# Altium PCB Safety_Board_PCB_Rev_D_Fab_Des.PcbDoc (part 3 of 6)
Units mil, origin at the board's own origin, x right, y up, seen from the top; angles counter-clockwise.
Board outline 11000 x 4400 mil, 6 copper layers (L1-TOP, L2-Plane, L3-Signal, L4-Signal, L5-Plane, L6-BOT); 712 components, 540 nets, 2214 pads, 875 vias.
Unrouted connection lines stored in the file: 3.
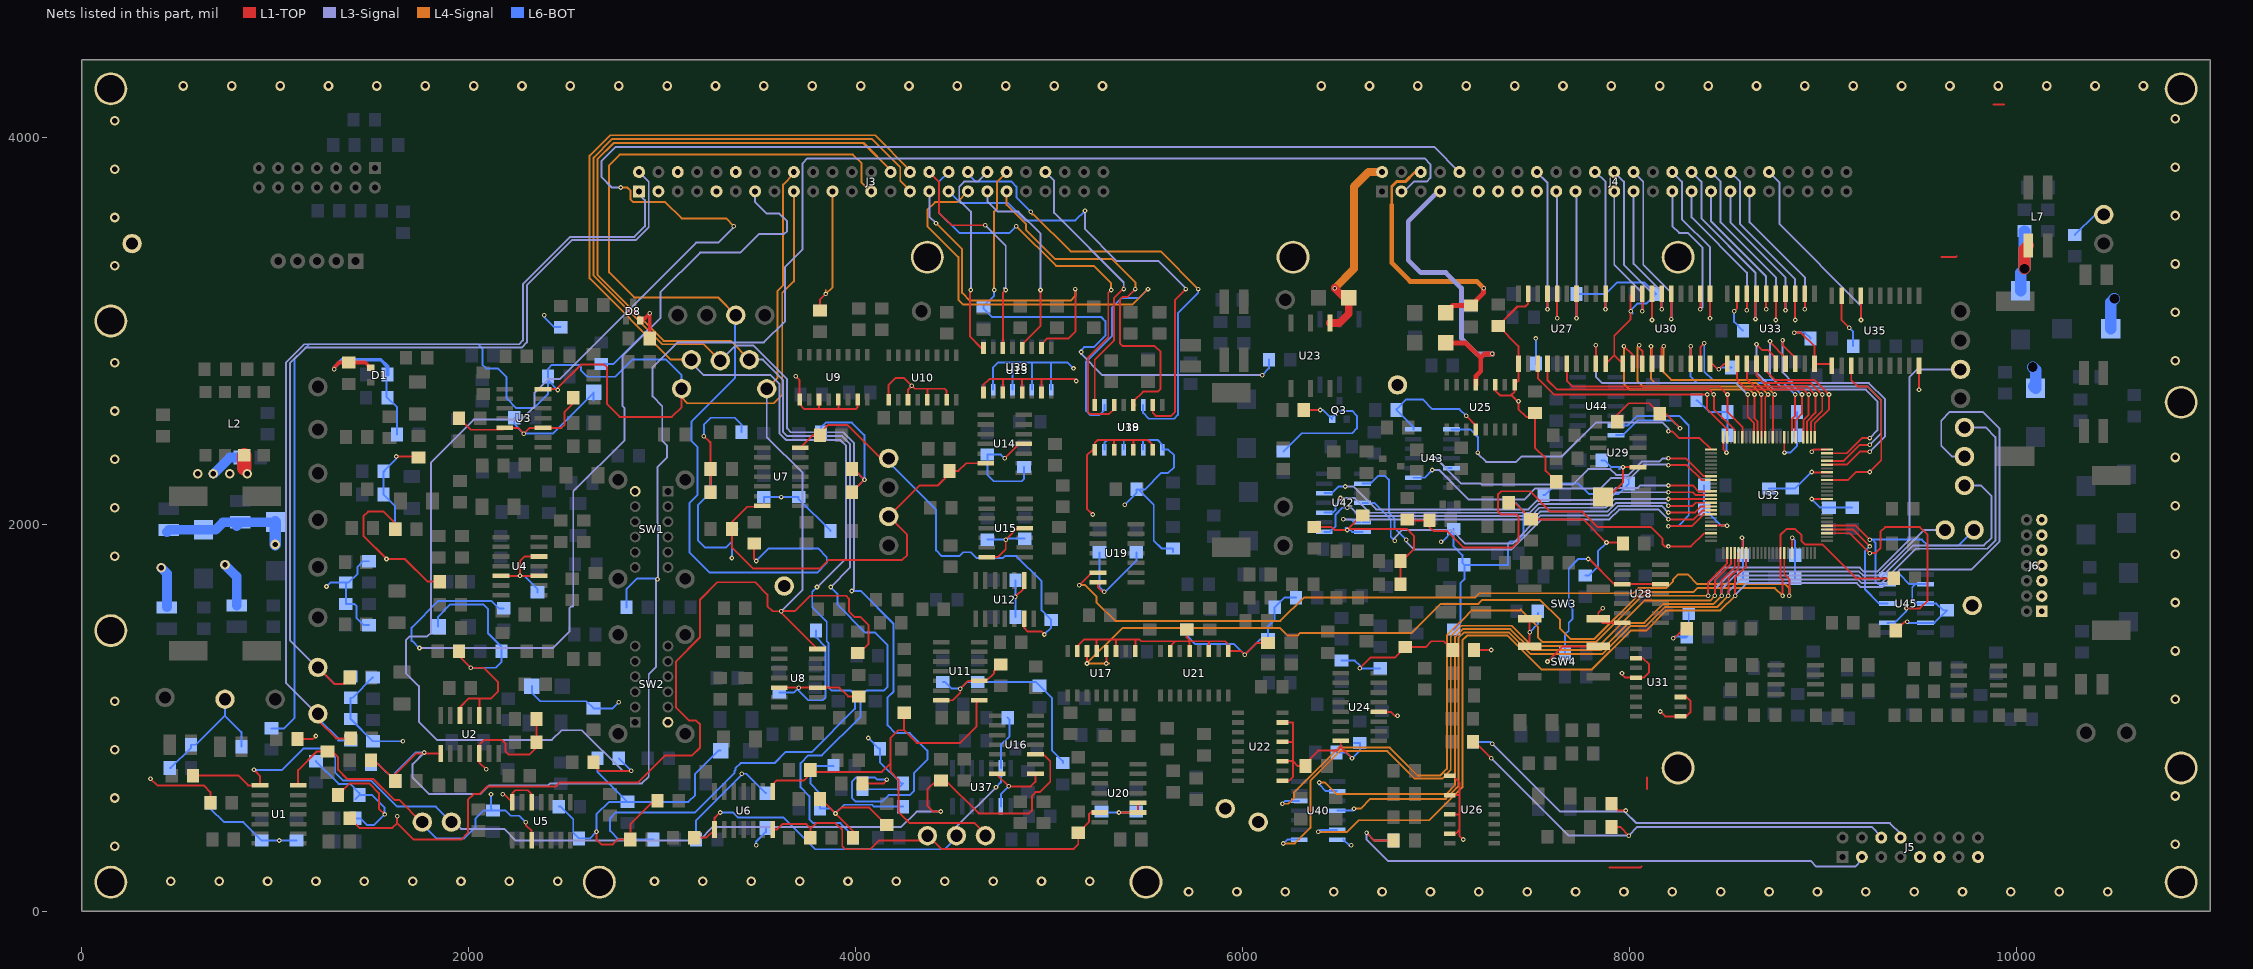
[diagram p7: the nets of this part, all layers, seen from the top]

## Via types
v1: diameter 24, hole 12, L1-TOP to L6-BOT, 720 vias
v2: diameter 50, hole 28, L1-TOP to L6-BOT, 138 vias
v3: diameter 28, hole 50, L1-TOP to L6-BOT, 17 vias

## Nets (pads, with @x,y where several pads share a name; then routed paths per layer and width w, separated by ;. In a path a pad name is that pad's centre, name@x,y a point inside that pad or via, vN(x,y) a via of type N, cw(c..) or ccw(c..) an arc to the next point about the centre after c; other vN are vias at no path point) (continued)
AGND: C3.1 C5.1 C6.1 C7.1 C10.1 C12.1 C15.1 C16.1 C19.1 C23.1 C24.1 C44.1 C45.1 C46.1 C47.1 C48.1 C49.1 C50.2 C51.1 C52.1 C53.1 C54.1 C55.1 C56.1 C57.1 C58.1 C59.1 C60.1 C61.1 C62.1 C67.1 C68.1 C71.1 C74.1 C75.1 C76.1 C77.1 C78.1 C79.1 C80.1 C81.1 C83.1 C84.1 C85.1 C86.1 C87.1 C88.1 C89.1 C90.1 C91.1 C92.1 C93.1 C94.1 C95.1 C96.1 C97.1 C98.1 C99.1 C100.1 C101.1 C102.1 C103.1 C107.1 D1.1 D8.2 D19.A D22.A D24.A D26.A J3.3 J3.6 J3.9 J3.12 J4.11 J4.13 J4.15 J4.17 L2.3 R3.1 R5.1 R23.1 R38.1 R45.1 R49.1 R54.1 R55.1 R63.1 R67.1 R68.1 R72.1 R81.1 R188.1 R189.1 R191.1 R193.1 R199.1 R200.1 R204.1 R205.2 R206.1 R208.1 R209.2 R227.1 R234.1 R237.1 R243.1 R244.1 R251.1 R254.1 R255.1 R257.1 R259.1 R285.1 SW1.7 SW2.7 TP3.1 TP24.1 TP33.1 TP38.1 U2.5 U2.10 U2.12 U3.5 U3.10 U4.5 U4.10 U4.12 U5.5 U5.7 U8.5 U8.10 U11.7 U11.10 U12.9 U14.11 U15.7 U15.11 U16.7 U16.8 U20.9 U20.10 U37.9 | length 25279.1
  L1-TOP w10: v1(355,685) 390,650 630,650 664.88,615.12 R3.1@664.88,560 ; R5.1@1115.12,890 1195,890 v1(1210,905) ; C5.1@1324.88,600 1384.88,660 1485,660 1535,610 1535,530 v1(1565,500) ; C7.1@1619.53,1973.11 1619.53,2005.47 1560,2065 1480,2065 1455,2040 1455,1940 v1(1575,1820) 1670,1820 1786.89,1703.11 C10.1@1849.53,1703.11 ; v1(1625,2350) 1734.88,2350 C6.1@1740,2344.88 ; C12.1@1949.53,2548.11 1949.65,2548.11 2009.65,2488.11 2176.22,2488.11 U3.5@2186.22,2498.11 2254.65,2498.11 v1(2284.65,2468.11) 2314.65,2498.11 2478.11,2498.11 2495,2515 2495,2580 2539.53,2624.53 R38.1@2539.53,2653.11 R38.1@2539.65,2653.11 ; R23.1@1949.76,1343.11 1949.76,1317.99 v1(2009.65,1258.11) 2076.89,1258.11 2150,1185 2150,1135 2115,1100 2000,1100 1954.65,1054.65 U2.12@1954.65,1011.54 ; U2.10@2054.65,1011.54 2054.65,1099.65 2055,1100 ; v1(2089.65,733.11) 2054.65,768.11 2054.65,859.65 2080,885 2170,885 2190,865 2190,825 2205,810 2315,810 2349.76,844.76 C15.1@2349.76,993.11 ; U4.5@2166.22,1733.11 v1(2264.65,1733.11) ; v1(2175,605) 2183.43,605 U5.7@2225,563.43 ; U5.7@2221.57,563.43 U5.7@2225,563.43 ; U5.5@2325,563.43 2325,605 2305,625 2240,625 2225,610 U5.7@2225,563.43 ; U4.10@2363.07,1733.11 v1(2264.65,1733.11) ; U4.12@2363.07,1833.11 2289.65,1833.11 2264.65,1808.11 v1(2264.65,1733.11) ; v1(2660,410) 2660,370 2685,345 2745,345 2770,370 R45.1@2834.88,370 2834.88,449.88 2955,570 R49.1@2974.88,570 ; v1(3215,2455) 3244.88,2425.12 3249.88,2425.12 R55.1@3249.88,2165 ; U8.5@3605,1155 3915,1155 3960.12,1109.88 C23.1@4015,1109.88 ; R63.1@3815.12,580 3820,580 3985.12,414.88 R72.1@3985.12,380 ; v1(3895,505) 3925,535 4070,535 4160,445 R81.1@4160,444.88 ; R68.1@3980.12,2165.12 v1(4045,2230) R67.1@4000,2275 ; U11.7@4441.57,1090.12 4500.12,1090.12 4540,1130 v1(4540,1150) 4580.12,1190.12 4675.12,1190.12 4715,1230 4715,1240.12 C24.1@4750,1275.12 ; U11.10@4633.31,1185 U11.10@4638.43,1190.12 ; U15.7@4676.57,1830 4735,1830 4775,1870 v1(4775,1920) 4835,1980 U15.11@4873.43,1980 ; U16.7@4731.57,710 4731.57,703.43 v1(4790,645) 4905,645 4928.43,668.43 U16.8@4928.43,710 ; v1(4770,2340) 4845,2415 U14.11@4868.43,2415 ; v1(4825,1625) 4870,1670 U12.9@4870,1708.43 ; v1(5360,510) U20.9@5458.43,510 U20.10@5458.43,560
  L1-TOP w20: v1(1305,2800) 1305,2810 1330.12,2835.12 1465.04,2835.12 D1.1@1492.76,2807.4 ; D8.2@2887.4,3052.76 2897.76,3052.76 v1(2935,3090) 2935.12,3089.88 C19.1@2935.12,2960
  L1-TOP w75: 840,2290 L2.3@840,2356.61
  L6-BOT w10: R189.1@454.88,740 460,740 565.12,845.12 R188.1@565.12,860 590,860 740,1010 ; C47.1@664.88,595.12 664.88,530.12 735,460 834.88,460 C51.1@930,364.88 C52.1@1110,364.88 ; TP3.1@740,1095 740,1010 ; R191.1@825.12,850 825.12,924.88 740,1010 ; R199.1@1210,775.12 1327.12,658 1387,658 1435.12,609.88 R208.1@1435.12,600 ; v1(1264.65,1678.11) 1284.53,1697.99 1377.99,1697.99 1425,1745 1425,1780 1453.23,1808.23 R206.1@1484.65,1808.23 ; C53.1@1364.65,1697.99 C56.1@1364.65,1588.23 1406.77,1588.23 1420,1575 1420,1515 1457.01,1477.99 C61.1@1484.65,1477.99 ; R200.1@1415.12,480 1440,480 1475,445 1510,445 v1(1565,500) 1565,535 1500,600 R208.1@1435.12,600 ; R208.1@1415.12,580 R208.1@1435.12,600 ; C62.1@1504.65,1208.23 1399.41,1102.99 C54.1@1389.65,1102.99 1389.65,993.11 1504.65,878.11 R209.2@1504.65,877.99 1659.53,877.99 v1(1659.65,878.11) ; C58.1@1564.65,2273.11 C58.1@1559.76,2273.11 ; C59.1@1574.65,2738.11 1574.65,2658.23 1629.53,2603.35 R204.1@1629.53,2463.11 ; R205.2@1619.53,1973.11 1619.53,2093.35 C55.1@1559.76,2153.11 C58.1@1559.76,2273.11 ; v1(1625,2350) 1625,2338.35 C58.1@1559.76,2273.11 ; D19.A@1841.5,1470 1841.5,1521.5 1905,1585 2075,1585 2100,1560 2100,1435 2169.76,1365.24 2169.76,1288.23 2139.65,1258.11 v1(2009.65,1258.11) ; C68.1@2234.88,2550 2234.88,2517.87 v1(2284.65,2468.11) 2433.11,2468.11 D24.A@2644.65,2679.65 ; v1(2264.65,1733.11) 2286.89,1733.11 2354.65,1665.35 C71.1@2354.65,1647.99 ; D22.A@2326.15,1163.11 2326.15,1128.85 2370,1085 2607.87,1085 R234.1@2644.65,1048.23 2743.23,1048.23 v1(2775,1080) ; v1(2390,3080) 2390,3070 2442.01,3017.99 R227.1@2474.65,3017.99 ; C74.1@2464.88,540 2475,540 2540,475 2540,405.12 C75.1@2570.12,375 2625,375 v1(2660,410) ; 2644.65,2639.65 D24.A@2644.65,2681.61 ; v1@2664.88,410 v1(2660,410) ; C77.1@2664.88,790 2664.88,720.24 R237.1@2820,565.12 ; C76.1@2684.65,2827.99 2747.99,2827.99 2935,3015 v1(2935,3090) ; C78.1@3174.88,370 3174.88,469.88 3410,705 v1(3410,710) 3435.12,710 C83.1@3535.12,610 C83.1@3535,610 ; v1(3215,2455) 3215,2515 3250,2550 3375,2550 3410.12,2514.88 R243.1@3410.12,2475 ; C79.1@3249.88,2285 C80.1@3249.88,2165 3185,2100.12 3185,1915 3220,1880 3330,1880 3360.12,1910.12 ; D26.A@3301.5,830 3290,830 3170,710 3170,600 3135.12,565.12 2725.12,565.12 2660,500 v1(2660,410) ; v1(3360,1825) 3360.12,1825.12 R244.1@3360.12,1975 R244.1@3390,1975 ; v1(3485,340) 3485,360 3535.12,410.12 C84.1@3535.12,430 ; C81.1@3525,2110 C81.1@3525,2139.88 ; C81.1@3525.12,2140 C81.1@3525,2139.88 ; C85.1@3605,1129.88 3679.88,1129.88 v1(3705,1155) 3705,1140 3755,1090 3830,1090 3843,1103 3843,1367 3794.88,1415.12 R255.1@3794.88,1450 ; R254.1@3819.88,2475 3819.88,2499.88 3845,2525 3980,2525 4045,2460 v1(4045,2230) ; R257.1@3869.88,1965 3705,2129.88 C87.1@3705,2139.88 3704.88,2140 v1(3615,2140) 3614.88,2139.88 C81.1@3525,2139.88 ; R259.1@3884.88,750 3785.12,750 R251.1@3765.12,730 3765.12,659.88 3815.12,609.88 C86.1@3815.12,530 3870,530 v1(3895,505) 3940,550 4084.04,550 4094.04,540 C91.1@4244.88,540 ; C89.1@3980.12,2165 3980.12,2165.12 v1(4045,2230) ; C88.1@3980.12,2285 3990,2285 v1(4045,2230) ; C90.1@4035.12,630 4214.88,630 C93.1@4244.88,660 4235,660 4124.88,770.12 C92.1@4124.88,840 4120,840 v1(4065,895) ; C94.1@4450,1185 4460,1185 4495,1150 v1(4540,1150) 4575,1185 C99.1@4630,1185 ; C99.1@4633.31,1185 4930.12,1185 5015,1100.12 5015,830 5070,775 R285.1@5070,765.12 ; C98.1@4680,1919.88 4774.88,1919.88 4779.88,1924.88 C101.1@4873.43,1924.88 ; U37.9@4750,541.57 4750,605 v1(4790,645) ; v1@4770,2335 v1(4770,2340) 4750.12,2359.88 C97.1@4680,2359.88 4680,2255 4713,2222 4857,2222 4870,2235 C100.1@4870,2294.88 ; C96.1@4825.12,1520 4825.12,1624.88 v1(4825,1625) 4825.12,1625.12 C95.1@4825.12,1710 ; C103.1@5270,514.88 5274.88,510 5445.12,510 C107.1@5450,514.88
  L6-BOT w20: v1(1305,2800) 1305,2810 1345,2850 1545,2850 1579.76,2815.24 C59.1@1579.76,2773.11
  L6-BOT w50: v2(410,1775) 440,1745 C45.1@440,1570.12 ; C44.1@440,1959.88 451.1,1970.98 690.98,1970.98 729.88,2009.88 998.9,2009.88 C50.2@1000,2010.98 ; v2(680,2260) 765,2345 R193.1@814.88,2345 ; v2(740,1790) 800,1730 C49.1@800,1580.12 ; C48.1@800,1989.88 C48.1@820,2009.88
  L6-BOT w60: v2(1000,1895) C50.2@1000,2010.98
  other v1: 1019.88,364.88
  other v2: 600,2260 765,2260 855,2260
BDEC: R2.2 R91.1 TP14.1 U1.1 U16.10 | length 5561.3
  L1-TOP w10: R2.2@575.12,700 810,700 860,650 U1.1@921.57,650 921.57,698.43 v1(890,730) ; v1(4440,515) 4400,515 4370,545 4370,630 4414.88,674.88 4465.12,674.88 4635,505 4895,505 4910,520 4910,595 4930,615 4950,615 5005,670 5005,775 4970,810 U16.10@4928.43,810
  L3-Signal w10: TP14.1@1910,460 1925,460 1960,425 2183.34,425 2243.34,365 3190,365 3260,435 4235,435 4315,515 v1(4440,515)
  L6-BOT w10: v1(890,730) 1035,730 1145,840 1265,840 1310,795 1310,715 1350,675 1495,675 1630,540 1830,540 TP14.1@1910,460
BHA: R6.2 R221.1 TP13.1 U1.14 U5.10 | length 1826.7
  L1-TOP w10: U1.14@1118.43,650 1118.43,728.43 1215.12,825.12 1294.88,825.12 1325,795 1325,730 1372,683 1507,683 1615,575 1640,575 1755,460 TP13.1@1760,460 ; v1(2295,460) 2295,445 2325,415 U5.10@2325,366.57
  L6-BOT w10: TP13.1@1760,460 1760,450 1835,375 1975,375 2035,435 2035,480 2075.12,520.12 2189.88,520.12 2216.77,493.23 2261.77,493.23 v1(2295,460) ; v1@2115,600 2115,530.12 R221.1@2125,520.12
  other v1: 2115,605
"BRAKE EN IN": J3.21 R65.1 | length 666.8
  L1-TOP w10: R65.1@3815,3105.12 3815,3160 v1(3845,3190) v1@3850,3190
  L4-Signal w10: 3845,3210 v1(3845,3190) 3880,3225 J3.21@3880,3720
"BRAKE ENABLE RELAY": D10.A J4.2 U23.4 | length 1053.6
  L1-TOP w40: U23.4@6450,3039.29 6499.29,3039.29 6548.5,3088.5 D10.A@6548.5,3170 ; v1(6475,3220) 6525,3170 D10.A@6565,3170
  L4-Signal w40: v1(6475,3220) 6575,3320 6575,3745 6650,3820 J4.2@6720,3820
BRAKE_RELEASE_IN_BUF: U19.6 U32.42 | length 4293.6
  L1-TOP w10: v1(5155,1685) 5220,1750 U19.6@5251.57,1750 ; U32.42@8798.74,1850.79 8798.74,1741.26 8825,1715 v1(8825,1630)
  L4-Signal w10: v1(5155,1685) 5185,1685 5245,1625 5245,1595 5340,1500 6195,1500 6317,1622 7202,1622 7223,1643 8018,1643 8045,1670 8190,1670 8224.15,1704.15 8224.15,1714.15 8250,1740 8300,1740 8350,1690 8805,1690 8825,1670 v1(8825,1630)
CHASSIS: pad. TP1.1 | length 364.1
  L1-TOP w10: 7895,225 8055,225 8060,230 ; 8090,630 8090,690 ; 9610,3380 9685,3380 9690,3385 ; 9880,4170 9935,4170
  other v2: 5720,100 5970,100 6220,100 6470,100 6720,100 6970,100 7220,100 7470,100 7720,100 7970,100 8220,100 8470,100 8720,100 8970,100 9220,100 9470,100 9720,100 9970,100 10220,100 10470,100 460,155 710,155 960,155 1210,155 1460,155 1710,155 1960,155 2210,155 2460,155 2960,155 3210,155 3460,155 3710,155 3960,155 4210,155 4460,155 4710,155 4960,155 5210,155 170,335 10820,345 170,585 10820,595 170,835 170,1085 10820,1095 10820,1345 10820,1595 170,1835 10820,1845 170,2085 10820,2095 170,2335 10820,2345 170,2585 170,2835 10820,2845 170,3085 10820,3095 170,3335 10820,3345 170,3585 10820,3595 170,3835 10820,3845 170,4085 10820,4095 525,4265 775,4265 1025,4265 1275,4265 1525,4265 1775,4265 2025,4265 2275,4265 2525,4265 2775,4265 3025,4265 3275,4265 3525,4265 3775,4265 4025,4265 4275,4265 4525,4265 4775,4265 5025,4265 5275,4265 6405,4265 6655,4265 6905,4265 7155,4265 7405,4265 7655,4265 7905,4265 8155,4265 8405,4265 8655,4265 8905,4265 9155,4265 9405,4265 9655,4265 9905,4265 10155,4265 10405,4265 10655,4265
CPLD_CLK: R348.1 U28.3 U28.12 | length 1017.9
  L1-TOP w10: v1(7785,1820) 7790,1820 7920,1690 U28.12@8158.43,1690
  L4-Signal w10: v1(7785,1820) v1@7790,1820
  L6-BOT w10: R348.1@7664.88,1330 7664.88,1429.88 7685,1450 7685,1490 7705,1510 7705,1560 7685,1580 7685,1770 7735,1820 v1(7785,1820)
"DEC EMERG N": J3.38 U13.8 | length 1072.8
  L1-TOP w10: v1(4595,3210) 4595,3205 4590,3200 4590,2970 4649.84,2910.16 U13.8@4660,2910.16
  L3-Signal w10: v1(4595,3210) 4595,3615 4535,3675 4535,3745 4560,3770 4630,3770 J3.38@4680,3820
"DEC EMERG N LATCH": J4.37 U33.14 | length 819.2
  L1-TOP w10: v1(8805,3105) U33.14@8805,3191.1
  L3-Signal w10: J4.37@8520,3720 8520,3560 8805,3275 v1(8805,3105)
"DEC EMERG S": J3.39 U18.4 | length 1896.6
  L1-TOP w10: v1(5445,3215) 5405,3175 5380,3175 5365,3160 5365,2935 5380,2920 5545,2920 5575,2890 5575,2700 5560,2685 5485,2685 5435,2635 U18.4@5435,2615.16 U18.4@5445.16,2615.16
  L4-Signal w10: J3.39@4780,3720 4780,3650 4880,3550 4880,3520 5030,3370 5325,3370 5445,3250 v1(5445,3215)
"DEC EMERG S LATCH": J4.38 U33.13 | length 1039.9
  L1-TOP w10: v1(8855,3055) U33.13@8855,3191.1
  L3-Signal w10: J4.38@8520,3820 8570,3770 8570,3550 8855,3265 v1(8855,3055)
"DEC OS LATCH": J4.19 U27.16 | length 783.2
  L1-TOP w10: v1(7625,3065) U27.16@7625,3191.1
  L3-Signal w10: J4.19@7620,3720 7625,3715 v1(7625,3065)
"DEC STOP N": J3.36 U39.6 | length 2401.8
  L4-Signal w10: 4910,3600 4920,3600 5110,3410 5575,3410 v1(5770,3215)
  L6-BOT w10: J3.36@4580,3820 4580,3810 4620,3770 4805,3770 4830,3745 4830,3690 v1(4905,3615) ; U39.6@5485,2615.16 5485,2575 5515,2545 5645,2545 5665,2565 5665,3090 5770,3195 v1(5770,3215)
"DEC STOP N LATCH": J4.35 U33.16 | length 809.2
  L1-TOP w10: v1(8705,3110) U33.16@8705,3191.1
  L3-Signal w10: J4.35@8420,3720 8420,3565 8705,3280 v1(8705,3110)
"DEC STOP S": J3.37 U13.4 | length 1024.6
  L1-TOP w10: U13.4@4860,2910.16 4860,2930 4955,3025 v1(4955,3210)
  L3-Signal w10: J3.37@4680,3720 4680,3670 4735,3615 4840,3615 4955,3500 v1(4955,3210)
"DEC STOP S LATCH": J4.36 U33.15 | length 1039.9
  L1-TOP w10: v1(8755,3055) U33.15@8755,3191.1
  L3-Signal w10: J4.36@8420,3820 8470,3770 8470,3560 8755,3275 v1(8755,3055)
"DEC VEL FEEDBACK": J3.18 R7.1 R75.2 TP23.1 U8.14 | length 7167.6
  L1-TOP w10: R7.1@1385.12,480 1435.12,430 1605,430 1630,455 ; v1(1630,490) 1630,455 ; U8.14@3765,1355 U8.14@3801.85,1355 3615,1541.85 v1(3615,1550) ; R75.2@4010,1334.88 4019.88,1334.88 4065,1380 4065,1480 4025,1520 3995,1520 3965,1550 3965,1615 3950,1630 3765,1630 3685.2,1550.2 3615.2,1550.2 v1(3615,1550) ; 1630,455 1715,370 1960,370 1995,405 1995,575 2025,605 2055,605 2095,645 2450.96,645 2470.96,665 2875,665 3015,805 3155,805 3195,845 3195,965 3175,985 3140,985 3070,1055 3070,1290 3195,1415 3195,1610 3285,1700 3480,1700 3543.64,1636.36 3543.64,1576.36 3570,1550 v1(3615,1550)
  L4-Signal w10: TP23.1@3540,2700 3595,2755 3595,3205 3625,3235 3625,3755 3680,3810 J3.18@3680,3820
  L3-Signal w10: TP23.1@3540,2700 3540,2450 3725,2265 3725,1660 v1(3615,1550)
DEC_EMERG_N_LATCH: U32.74 U33.6 | length 1452.1
  L1-TOP w10: v1(8655,2930) 8685,2900 8715,2900 8755,2860 U33.6@8755,2828.9 ; U32.74@9019.21,2366.54 9121.54,2366.54 9200,2445 v1(9240,2445)
  L3-Signal w10: v1(8655,2930) 8655,2785 8745,2695 9220,2695 9280,2635 9280,2485 v1(9240,2445)
DEC_EMERG_NORTH_BUF_N: U32.14 U42.8 | length 2140.5
  L1-TOP w10: v1(8200,2130) 8420.47,2130 U32.14@8420.79,2130.32
  L3-Signal w10: v1(6540,2085) 6560,2085 6603,2042 7489.88,2042 7532.88,2085 7875,2085 7920,2130 v1(8200,2130)
  L6-BOT w10: U42.8@6421.57,1960 6450,1960 6480,1990 6480,2050 6515,2085 v1(6540,2085)
DEC_EMERG_S_LATCH: U32.72 U33.7 | length 1466
  L1-TOP w10: v1(8725,2945) 8725,2940 8805,2860 U33.7@8805,2828.9 ; U32.72@9019.21,2327.17 9107.17,2327.17 9190,2410 v1(9240,2410)
  L3-Signal w10: v1(8725,2945) 8725,2765 8778,2712 9228,2712 9300,2640 9300,2470 v1(9240,2410)
DEC_EMERG_SOUTH_BUF_N: U32.12 U42.12 | length 2126.9
  L1-TOP w10: v1(8200,2200) 8325,2200 8355.31,2169.69 U32.12@8420.79,2169.69
  L3-Signal w10: v1(6530,2195) 6570,2195 6689,2076 7475.79,2076 7524.79,2125 7865,2125 7927,2187 8042,2187 8055,2200 v1(8200,2200)
  L6-BOT w10: U42.12@6421.57,2160 6460,2160 6495,2195 v1(6530,2195)
DEC_LAB_SELECT: R181.1 U17.12 U17.14 U32.41 | length 5284
  L1-TOP w10: v1(5195,1280) U17.14@5195,1345.16 ; v1(5295,1280) U17.12@5295,1345.16 ; v1(8790,1630) 8790,1715 8779.06,1725.94 8779.06,1944.06 8810,1975 8855,1975 8888.13,1941.87 8888.13,1911.87 8905,1895 8995,1895 9170,1720 R181.1@9364.88,1720
  L4-Signal w10: 5310,1280 v1(5195,1280) 5378,1463 6192.96,1463 6230.96,1425 6285,1425 6298,1438 6873,1438 7023,1588 7218,1588 7239,1609 7536,1609 7640,1505 7640,1460 7693,1407 7817.96,1407 8060.96,1650 8330,1650 8350,1670 8750,1670 v1(8790,1630)
DEC_OVERSPEED_LATCH: U27.4 U32.97 | length 1240.4
  L1-TOP w10: U27.4@7575,2828.9 7575,2745 7625,2695 8410,2695 v1(8435,2670) 8435,2595 8542.83,2487.17 U32.97@8542.83,2449.21
DEC_OVERSPEED_N: TP47.1 U32.55 U45.6 | length 1125.4
  L1-TOP w10: U32.55@9019.21,1992.52 9167.48,1992.52 v1(9240,1920)
  L6-BOT w10: v1(9240,1920) 9510,1920 9540,1890 9700,1890 TP47.1@9780,1970 ; 9255,1920 9270,1905 9270,1705 9285,1690 U45.6@9331.57,1690
DEC_STOP_N_LATCH: U32.77 U33.4 | length 685.3
  L1-TOP w10: U33.4@8655,2828.9 8655,2770 8696,2729 8936,2729 v1(8995,2670) 8995,2585 8936.54,2526.54 U32.77@8936.54,2449.21
DEC_STOP_NORTH_BUF_N: U32.9 U43.2 | length 1727
  L1-TOP w10: v1(8200,2305) 8295,2305 8371.26,2228.74 U32.9@8420.79,2228.74
  L3-Signal w10: v1(6980,2280) 7015,2280 7168,2127 7454.67,2127 7512.67,2185 7850,2185 7903,2238 8003,2238 8073,2308 8197,2308 v1(8200,2305)
  L6-BOT w10: U43.2@6881.57,2240 6940,2240 v1(6980,2280)
DEC_STOP_S_LATCH: U32.76 U33.5 | length 665
  L1-TOP w10: U33.5@8705,2828.9 8705,2790 8749,2746 8954,2746 v1(9030,2670) 9030,2595 8956.22,2521.22 U32.76@8956.22,2449.21
DEC_STOP_SOUTH_BUF_N: U32.16 U42.4 | length 2102.8
  L1-TOP w10: v1(8200,2060) 8335,2060 8365.94,2090.94 U32.16@8420.79,2090.94
  L3-Signal w10: v1(6785,1915) 6785,1930 6825,1970 7080,1970 7150,1900 7395.96,1900 7540.96,2045 7890,2045 7938,2093 8167,2093 v1(8200,2060)
  L6-BOT w10: U42.4@6618.43,2110 6680,2110 6765,2025 6765,1935 v1(6785,1915)
DGND: C25.1 C26.1 C27.1 C28.1 C29.1 C30.1 C31.1 C32.1 C33.1 C34.1 C35.1 C36.1 C37.1 C38.2 C39.1 C40.1 C42.1 C104.1 C105.1 C106.1 C108.1 C109.1 C114.1 C115.1 C116.1 C117.1 C118.1 C119.1 C120.1 C121.1 C122.1 C123.1 C124.1 C125.1 C126.1 C127.1 C128.1 C129.1 C130.1 C131.1 C132.1 C133.1 C134.1 C135.1 C136.1 C137.1 C138.1 C139.1 C140.1 C141.1 C142.1 C143.1 C144.1 C145.1 C146.1 C147.1 C148.1 C149.1 C150.1 C151.1 C152.1 C154.1 C155.1 C156.1 C157.2 C159.2 C161.2 J5.15 J6.1 J6.3 J6.5 J6.7 J6.9 J6.11 J6.13 L7.3 Q3.2 R128.2 R153.1 R161.1 R169.1 R374.1 R383.2 R387.1 SW3.1 SW3.3 SW4.1 SW4.3 TP34.1 TP48.1 TP50.1 U9.9 U9.11 U9.13 U9.15 U10.9 U10.11 U10.13 U10.15 U13.9 U13.11 U13.13 U13.15 U17.9 U17.11 U17.13 U17.15 U18.9 U18.11 U18.13 U18.15 U19.7 U21.9 U21.11 U21.13 U21.15 U22.9 U22.11 U22.13 U22.15 U24.8 U24.12 U25.4 U25.9 U25.11 U26.9 U26.11 U26.13 U26.15 U27.1 U27.10 U27.19 U28.7 U29.1 U30.1 U30.10 U30.19 U31.2 U31.4 U31.9 U31.11 U32.21 U32.31 U32.44 U32.62 U32.69 U32.75 U32.84 U32.100 U33.1 U33.10 U33.19 U35.1 U35.10 U35.19 U38.9 U38.11 U38.13 U38.15 U39.9 U39.11 U39.13 U39.15 U40.7 U42.7 U43.7 U44.7 U45.7 U45.9 U45.11 U45.13 | length 27059.8
  L1-TOP w10: v1(3690,2765) 3710,2745 3710,2620 3735,2595 4000,2595 4010,2605 U9.15@4010,2644.84 ; 3810,2595 U9.11@3810,2644.84 ; 3910,2595 U9.13@3910,2644.84 ; U10.9@4170,2642.84 4170,2720 4205,2755 4250,2755 4305,2700 4460,2700 4470,2690 U10.15@4470,2642.84 ; U10.11@4270,2642.84 4270,2695 v1(4290,2715) ; U10.13@4370,2642.84 4370,2700 ; U13.9@4660,2679.84 4660,2720 4690,2750 5130,2750 v1(5140,2740) ; U13.11@4760,2679.84 4760,2750 ; U13.13@4860,2679.84 4860,2750 ; U13.15@4960,2679.84 4960,2750 ; U17.15@5145,1345.16 5145,1370 5180,1405 5465,1405 5475,1395 5910,1395 5925,1380 U21.9@5925,1345.16 5989.84,1345.16 v1(6010,1325) 6070.12,1385.12 C26.1@6130,1385.12 ; v1(5225,2050) 5195,2080 5195,2355 5224.84,2384.84 U18.9@5235,2384.84 5235,2420 5250,2435 5510,2435 5535,2410 U18.15@5535,2384.84 ; U17.13@5245,1345.16 5245,1405 ; U19.7@5251.57,1700 5251.57,1673.43 5275,1650 v1(5285,1650) ; U18.11@5335,2384.84 5335,2435 ; U17.11@5345,1345.16 5345,1405 ; U18.13@5435,2384.84 5435,2435 ; 5440,1405 5445,1400 U17.9@5445,1345.16 ; U21.15@5625,1345.16 5625,1370 5650,1395 ; C25.1@5710,1454.88 5710,1415 5730,1395 ; U21.13@5725,1345.16 5725,1395 ; U21.11@5825,1345.16 5825,1395 ; C26.1@6095.12,1400.12 C26.1@6135,1400.12 ; U22.9@6205.16,675 6240,675 6260,695 6260,975 U22.15@6205.16,975 ; U22.11@6205.16,775 6260,775 6285,750 C28.1@6324.88,750 6324.88,764.88 6390,830 6488.15,830 6506.57,848.43 ; U22.13@6205.16,875 6260,875 ; R128.2@6305,2600.12 R128.2@6315.12,2590 v1(6400,2590) ; C27.1@6370,1985.12 6459.88,1985.12 6475,1970 v1(6540,1970) 6614.88,2044.88 C29.1@6620,2044.88 ; U24.8@6506.57,880 6506.57,848.43 ; v1@6545,1975 6850,1975 6885,1940 6885,1870 6825,1810 C30.1@6815.12,1810 C31.1@6815.12,1690 ; v1(6565,790) 6506.57,848.43 ; v1(6605,1255) 6660,1310 6785.12,1310 C32.1@6840,1364.88 6944.88,1364.88 6975,1395 7039.88,1395 R153.1@7084.88,1350 ; U24.12@6703.43,1030 6765,1030 6785,1010 v1(6800,1010) ; v1(7025,1910) v1@7030,1915 ; U26.15@7069.84,400 7100,400 7120,420 ; U26.13@7069.84,500 7120,500 ; U26.11@7069.84,600 7120,600 ; U26.9@7069.84,700 7085,700 7120,665 7120,390 v1(7140,370) ; v1(7155,2560) 7205,2510 U25.4@7205,2489.84 ; U25.11@7305,2720.16 7305,2690 7330,2665 7390,2665 7420,2635 v1(7425,2635) 7425,2595 7465.12,2554.88 R161.1@7510,2554.88 ; C33.1@7320,3024.88 7425,2919.88 7425,2740.16 U25.9@7405,2720.16 7405,2685 7385,2665 ; C33.1@7320,3025 7420,3125 7460,3125 7475,3140 U27.19@7475,3191.1 ; C34.1@7375.12,2110 7405.12,2110 C35.1@7490,2025.12 7759.88,2025.12 v1@7885,1900 ; SW4.1@7482.83,1368.74 SW3.3@7482.83,1511.26 ; R161.1@7510,2574.88 7510,2395 7565,2340 7565,2274.88 C36.1@7619.88,2220 ; v1(7575,1290) 7653.74,1368.74 SW4.3@7837.17,1368.74 ; v1(7860,1565) 7837.17,1542.16 SW3.1@7837.17,1511.26 7858.43,1490 U28.7@7961.57,1490 ; C38.2@7861.57,2140 7890,2140 7964.96,2214.96 v1(7964.96,2295.04) U29.1@8042.32,2295.04 ; U27.10@7876.1,2828.9 U27.10@7875,2828.9 7920,2873.9 ; v1(7880,1905) 7959.88,1905 C39.1@7964.88,1900 ; C37.1@7935.12,2530 7935.12,2565.12 7995,2625 8100.12,2625 R169.1@8155.12,2570 8185,2570 v1(8260,2495) ; v1(7960,1230) 7960,1225 7978.08,1206.92 8071.92,1206.92 8100,1235 8100,1275 8068.08,1306.92 U31.2@8032.81,1306.92 ; U30.1@7963.9,2828.9 U30.1@7965,2828.9 7920,2873.9 ; U30.19@8015,3191.1 8005,3181.1 8005,3060 7920,2975 7920,2873.9 ; v1(8157.96,1031.92) 8182.96,1006.92 8292.96,1006.92 8312.96,1026.92 8312.96,1086.92 8292.96,1106.92 U31.11@8263.12,1106.92 ; v1(8225,1410) 8230,1410 8280,1460 C40.1@8294.88,1460 ; U30.10@8415,2828.9 8426.1,2828.9 8455,2800 v1(8460,2800) 8488.9,2828.9 U33.1@8505,2828.9 ; U32.21@8420.79,1992.52 v1(8502.48,1992.52) ; U32.100@8483.78,2449.21 8483.78,2386.22 v1(8500,2370) ; v1(8540,3100) 8555,3115 U33.19@8555,3191.1 ; v1(8580,1930) 8582.2,1927.8 U32.31@8582.2,1850.79 ; U32.84@8798.74,2449.21 8798.74,2366.26 8800,2365 v1(8800,2370) ; U32.44@8838.11,1850.79 8838.11,1933.11 8840,1935 v1(8840,1930) ; v1(8850,2990) 8885,2990 8955,2920 U33.10@8955,2828.9 9035,2828.9 U35.1@9045,2818.9 ; v1(8940,2130) 8940.32,2130.32 U32.62@9019.21,2130.32 ; v1(8940,2270) 8941.89,2268.11 U32.69@9019.21,2268.11 ; v1(8940,2375) 8951.22,2386.22 U32.75@9019.21,2386.22 ; U35.19@9095,3181.1 9095,3055 v1(9135,3015) ; C42.1@9375.12,1450 9420.12,1495 v1(9435,1495) ; v1(9495,2695) U35.10@9495,2818.9
  L1-TOP w60: v3(10040,3320) 10040,3420 L7.3@10060,3440
  L6-BOT w10: U38.15@4710,2694.84 4710,2810 4735,2835 5095,2835 v1(5125,2805) ; U38.13@4810,2694.84 4810,2835 ; U38.11@4910,2694.84 4910,2835 ; U38.9@5010,2694.84 5010,2835 ; C105.1@5260,1854.88 5260,1675 v1(5285,1650) ; U39.15@5285,2384.84 5285,2420 5300,2435 5560,2435 5585,2410 U39.9@5585,2384.84 5615.16,2384.84 5645,2355 5645,2295 5615,2265 5580,2265 5495,2180 C104.1@5450.24,2180 5450.24,2160.24 v1(5390,2100) ; v1@5288.34,1650 5450,1811.66 C106.1@5450,1854.88 ; U39.13@5385,2384.84 5385,2435 ; C104.1@5460,2180 5540,2100 5540,1915 5580.12,1874.88 C108.1@5640,1874.88 C108.1@5640,1855 ; U39.11@5485,2384.84 5485,2435 ; C109.1@5710,1454.88 5710,1425 5755,1380 5955,1380 v1(6010,1325) 6090.12,1405.12 C115.1@6130,1405.12 6130,1470 6165.12,1505.12 C114.1@6165.12,1570 6215.12,1620 C117.1@6274.88,1620 ; C116.1@6210,2375.12 6304.88,2470 6565,2470 6590,2495 6590,2560 6565,2585 6495,2585 6462.6,2552.6 Q3.2@6462.6,2542.76 6415.35,2590 v1(6400,2590) ; C118.1@6485.12,820 6535,820 v1(6565,790) 6605,830 C120.1@6605,869.88 C120.1@6574.88,869.88 ; C119.1@6510,1295.12 6579.88,1295.12 6605,1270 v1(6605,1255) 6709.88,1255 C122.1@6710,1255.12 ; U40.7@6520,370 6550,340 v1(6560,340) ; 6530,1980 v1@6540,1980 ; v1(6540,1970) 6555,1970 6565,1960 U42.7@6618.43,1960 ; U43.7@6881.57,2490 6881.57,2503.54 C121.1@6795.12,2590 6795.12,2595.12 6845,2645 6930,2645 6980,2595 7120,2595 v1(7155,2560) ; v1(7025,1910) 7025,1905 C123.1@7090,1970 ; C125.1@7090,1455.12 7125,1490.12 7125,1695 7145.12,1715.12 C124.1@7145.12,1790 ; C123.1@7090,1974.88 7090,1885 7135.12,1839.88 7135.12,1800 C124.1@7145.12,1790 ; C126.1@7375.12,2110 7410,2110 7450,2070 7450,1945 7415,1910 7380,1910 7370,1900 7370,1790 C124.1@7145.12,1790 ; v1(7482.83,1442.16) 7525.12,1484.45 C127.1@7525.12,1540 ; C128.1@7514.88,2830 7514.88,2959.88 v1(7515,2960) ; C130.1@7554.88,2150 7560,2150 7620,2210 7735,2210 7790,2155 7939.88,2155 C133.1@7994.88,2210 7994.88,2230.12 7964.96,2260.04 v1(7964.96,2295.04) 7904.96,2295.04 7870,2330 C132.1@7855.12,2330 ; C129.1@7725.12,3190 7875,3190 7935,3250 8075.12,3250 C134.1@8135.12,3190 8085.12,3140 8040,3140 8005,3105 v1(8005,3100) ; C131.1@7770,1735.12 7790.12,1735.12 7835,1780 7835,1860 v1(7880,1905) ; U44.7@7928.43,2460 7965,2460 8040,2535 8220,2535 v1(8260,2495) ; 7945,2285 7950,2285 ; v1@8000,3100 v1(8005,3100) ; 8015.12,3089.88 v1(8005,3100) ; v1(8225,1410) 8235,1420 C141.1@8294.88,1420 ; C141.1@8265,1415 8289.88,1415 8305.12,1430.24 C136.1@8305.12,1540 ; C135.1@8345.12,2640 8350,2640 8410,2580 C145.1@8504.88,2580 C137.1@8504.88,2460 8500,2455.12 v1(8500,2370) ; C142.1@8384.88,2200 C138.1@8384.88,2080 8472.36,1992.52 v1(8502.48,1992.52) ; v1(8460,2800) 8470,2810 C144.1@8524.88,2810 ; v1(8540,3100) 8540,3045.12 C143.1@8585.12,3000 ; v1(8580,1930) 8585.12,1924.88 C140.1@8585.12,1720 ; C146.1@8720,2185.12 C149.1@8840,2185.12 8855.12,2185.12 v1(8940,2270) ; v1(8800,2370) 8830,2370 8865.12,2405.12 C147.1@8865.12,2580 ; v1(8840,1930) 8855.12,1914.88 C151.1@8855.12,1720 ; v1(8850,2990) 8904.88,2990 C152.1@8934.88,2960 ; v1(8940,2130) 8984.88,2085.12 C155.1@9150,2085.12 ; v1(9135,3015) 9154.88,2995.12 R374.1@9154.88,2920 ; U45.7@9331.57,1740 9395,1740 9445,1690 U45.9@9528.43,1690 ; v1(9435,1495) 9440,1490 9574.88,1490 C156.1@9640,1555.12 9619.88,1555.12 9585,1590 9485,1590 9460,1615 9460,1675 9475,1690 ; R387.1@10300,3495.12 10300.12,3495.12 10405,3600 TP50.1@10450,3600
  L6-BOT w60: C157.2@10020,3205.98 10020,3300 ; v3(10040,3320) R383.2@10040,3514.88 ; v3(10082.96,2811.92) 10097.96,2796.92 C159.2@10097.96,2702.9 C159.2@10087.96,2712.9 ; C161.2@10485.98,3010 10485.98,3145.98 v3(10505,3165)
"DOME1 CURRENT": J3.28 R252.1 TP22.1 | length 6741.3
  L4-Signal w10: TP22.1@3450,2850 3353,2947 3007.04,2947 2665,3289.04 2665,3885 2750,3970 4040,3970 4180,3830 J3.28@4180,3820
  L3-Signal w10: TP22.1@3450,2850 3520,2850 3625,2745 3625,2475 3645,2455 3930,2455 3970,2415 3970,1775 v1(3870,1675)
  L6-BOT w10: v1(3870,1675) 3905,1640 3905,1585 4050,1440 4100,1440 4165,1375 4165,1160 4145,1140 4055,1140 4025,1110 4025,1005 3824.62,804.62 3754.62,804.62 3715,765 3715,640 3760,595 3760,475 3780,455 3920,455 3985.12,389.88 R252.1@3985.12,380
"DOME1 OC LATCH": J4.24 U27.11 | length 816.8
  L1-TOP w10: v1(7875,3110) U27.11@7875,3191.1
  L3-Signal w10: J4.24@7820,3820 7825,3820 7875,3770 v1(7875,3110)
DOME1_OVERCURRENT_LATCH: U27.9 U32.92 | length 1315.9
  L1-TOP w10: U27.9@7825,2828.9 v1(7825,2925) ; v1(8610,2670) 8610,2555 8641.26,2523.74 U32.92@8641.26,2449.21
  L3-Signal w10: v1(7825,2925) 7825,2762 7858,2729 8551,2729 v1(8610,2670)
DOME1_OVERCURRENT_N: TP44.1 U32.30 U40.4 | length 5510
  L1-TOP w10: v1(8510,1630) 8510,1720 8562.52,1772.52 U32.30@8562.52,1850.79
  L4-Signal w10: v1(6575,530) 6610,530 6660,580 7049.92,580 7115,645.08 7115,1411.92 7144.08,1441 7375.92,1441 7486.92,1330 7860,1330 8003,1473 8083,1473 8181,1571 8451,1571 v1(8510,1630)
  L3-Signal w10: v1(8510,1630) 8510,1650 8575,1715 9177.88,1715 9197.88,1695 9300,1695 9478,1873 9848,1873 9890,1915 9890,2450 9840,2500 TP44.1@9730,2500
  L6-BOT w10: U40.4@6488.43,520 6570,520 6575,525 v1(6575,530)
"DOME2 CURRENT": J3.29 R76.1 TP19.1 | length 7217.2
  L1-TOP w10: R76.1@4035.12,660 4145,660 4165,680 v1(4160,680)
  L4-Signal w10: TP19.1@3300,2845 3215,2930 3000,2930 2645,3285 2645,3895 2740,3990 4085,3990 4230,3845 4230,3775 4280,3725 J3.29@4280,3720
  L3-Signal w10: TP19.1@3300,2845 3378,2923 3472,2923 3645,2750 3645,2495 3665,2475 3935,2475 3990,2420 3990,1665 v1(3980,1655)
  L6-BOT w10: v1(3980,1655) 4025,1655 4195,1485 4195,1135 4165,1105 4165,960 4205,920 4280,920 4370,830 4370,783.34 4300,713.34 4300,620 4280,600 4170,600 4137,567 3998,567 3980,585 3980,670 4000,690 4100,690 4110,680 v1(4160,680)
"DOME2 OC LATCH": J4.25 U30.18 | length 771.2
  L1-TOP w10: v1(8065,3100) U30.18@8065,3191.1
  L3-Signal w10: J4.25@7920,3720 7920,3340 8065,3195 v1(8065,3100)
DOME2_OVERCURRENT_LATCH: U30.2 U32.91 | length 1229.9
  L1-TOP w10: v1(7970,2920) 8015,2875 U30.2@8015,2828.9 ; v1(8645,2670) 8645,2545 8660.94,2529.06 U32.91@8660.94,2449.21
  L4-Signal w10: v1(7970,2920) 7970,2725 8000,2695 8620,2695 v1(8645,2670)
DOME2_OVERCURRENT_N: TP45.1 U32.32 U40.6 | length 6308.7
  L1-TOP w10: v1(8545,1630) 8545,1725 8601.89,1781.89 U32.32@8601.89,1850.79
  L4-Signal w10: v1(6390,410) 6540,410 6600,470 6963.96,470 7113,619.04 7114.04,619.04 7135,640 7135,1400 7159,1424 7368.88,1424 7542.88,1250 7805,1250 8005,1450 8085,1450 8189,1554 8469,1554 v1(8545,1630)
  L3-Signal w10: v1(8545,1630) 8545,1635 8605,1695 9173.83,1695 9193.83,1675 9305,1675 9395,1765 9765,1765 9910,1910 9910,2495 9825,2580 9655,2580 9610,2535 9610,2405 9665,2350 TP45.1@9730,2350
  L6-BOT w10: v1(6390,410) 6400,420 U40.6@6488.43,420
"DOME3 CURRENT": J3.30 R239.1 TP18.1 | length 7701
  L4-Signal w10: TP18.1@3150,2850 3045,2850 2625,3270 2625,3905 2730,4010 4100,4010 4280,3830 J3.30@4280,3820
  L3-Signal w10: TP18.1@3180,2850 TP18.1@3150,2850 3150,2835 3215,2770 3560,2770 3605,2725 3605,2470 3635,2440 3635.96,2440 3640.96,2435 3920,2435 3950,2405 3950,1825 v1(3800,1675)
  L6-BOT w10: 2765,370 R239.1@2954.88,370 ; 2775,370 2730,415 2730,480 2760,510 3170,510 3373.13,713.13 3373.13,723.53 3377.77,728.16 3377.77,737.77 3405,765 3580,765 3636.62,821.62 3771.62,821.62 3995,1045 3995,1120 3975,1140 3875,1140 3860,1155 3860,1385 3850,1395 3850,1495 3775,1570 3775,1650 v1(3800,1675)
"DOME3 OC LATCH": J4.26 U30.17 | length 981.9
  L1-TOP w10: v1(8115,3055) U30.17@8115,3191.1
  L3-Signal w10: J4.26@7920,3820 7970,3770 7970,3340 8115,3195 v1(8115,3055)
DOME3_OVERCURRENT_LATCH: U30.3 U32.90 | length 1181.5
  L1-TOP w10: v1(8050,2925) 8050,2910 8065,2895 U30.3@8065,2828.9 ; v1(8680,2670) 8680.63,2669.37 U32.90@8680.63,2449.21
  L4-Signal w10: v1(8050,2925) 8040,2915 8040,2740 8068,2712 8638,2712 v1(8680,2670)
DOME3_OVERCURRENT_N: TP46.1 U32.29 U40.2 | length 5369
  L1-TOP w10: v1(8475,1630) 8475,1710 8542.83,1777.83 U32.29@8542.83,1850.79
  L4-Signal w10: v1(6395,665) 6425,665 6485,605 7050.88,605 7098,652.12 7098,1418.96 7137.04,1458 7382.96,1458 7490.96,1350 7855,1350 7995,1490 8075.96,1490 8173.96,1588 8433,1588 v1(8475,1630)
  L3-Signal w10: v1(8475,1630) 8475,1665 8545,1735 9181.92,1735 9201.92,1715 9290,1715 9465,1890 9830,1890 9870,1930 9870,2145 9815,2200 TP46.1@9730,2200
  L6-BOT w10: v1(6395,665) 6395,655 6430,620 U40.2@6488.43,620
"DOME AMP": D12.K J4.6 R151.1 | length 1366.9
  L1-TOP w25: D12.K@7050,3093.5 7086.62,3130.12 R151.1@7180,3130.12 7245,3195.12 v1(7245,3220)
  L4-Signal w15: 6770,3650 6770,3745 6795,3770 6840,3770 6890,3820 J4.6@6920,3820
  L4-Signal w25: 6770,3650 6770,3350 6865,3255 7210,3255 v1(7245,3220)
"DOME AMP ENABLE & THERM STAT LATCH": J4.42 U35.17 | length 1087.9
  L1-TOP w10: v1(9195,3055) U35.17@9195,3181.1
  L3-Signal w10: J4.42@8720,3820 8775,3765 8775,3550 9195,3130 v1(9195,3055)
"DOME AMP RET": D12.A J4.7 U25.13 | length 1647.6
  L1-TOP w25: D12.A@7050,2936.5 7153.5,2936.5 7230,2860 ; U25.13@7205,2720.16 7205,2765 7230,2790 7230,2860 ; v1(7290,2880) 7250,2880 7230,2860
  L3-Signal w25: J4.7@7020,3720 7010,3720 6855,3565 6855,3365 6920,3300 7050,3300 7130,3220 7130,2960 7210,2880 v1(7290,2880)
DOME_AMP_ENABLE_&_THERM_STAT: U32.8 U43.12 | length 1738.7
  L1-TOP w10: v1(8200,2340) 8290,2340 8381.57,2248.43 U32.8@8420.79,2248.43
  L3-Signal w10: v1(6980,2345) 6995,2345 7130,2210 7230,2210 7235,2205 7705,2205 7785,2285 7900,2285 7930,2255 7995,2255 8065,2325 8155,2325 8170,2340 v1(8200,2340)
  L6-BOT w10: v1(6980,2345) 6995,2345 7050,2290 U43.12@7078.43,2290
DOME_AMP_ENABLE_&_THERM_STAT_LATCH: U32.67 U35.3 | length 905.1
  L1-TOP w10: U32.67@9019.21,2228.74 9128.74,2228.74 9170,2270 v1(9240,2270) 9300,2330 9300,2640 9228,2712 9178,2712 9145,2745 U35.3@9145,2818.9
DOME_AMP_ENABLE_N: R146.1 R150.2 U32.23 | length 2274.1
  L1-TOP w10: R146.1@6850,2024.88 6854.88,2020 R150.2@6964.88,2020 6964.88,1985.12 6985,1965 7055,1965 7140,1880 7395,1880 7425,1910 7425,2040 7415,2050 7335,2050 7320,2065 7320,2155 7335,2170 7485,2170 7590,2065 7755,2065 7835,1985 8110,1985 8170,1925 8170,1895 8180,1885 8315.96,1885 8384.11,1953.15 U32.23@8420.79,1953.15
  other v1: 8200,1885
"EAST CURRENT": J3.25 R58.1 TP20.1 | length 5424
  L1-TOP w10: R58.1@3475,1899.88 3475,1820 v1(3485,1810)
  L4-Signal w10: TP20.1@3380,3080 3288,3172 2854.17,3172 2725,3301.17 2725,3855 2780,3910 3985,3910 4030,3865 4030,3765 4075,3720 J3.25@4080,3720
  L6-BOT w10: 3375,3030 3375,2755 3150,2530 3150,2430 3183,2397 3183,2152.04 3140,2109.04 3140,1855 3245,1750 3800,1750 3850,1800 3850,1830 3805,1875 3550,1875 v1(3485,1810)
"EAST DRIVE+": C57.2 J3.1 R16.1 TP12.1 | length 4886.7
  L1-TOP w10: TP12.1@1220,1020 1220,987.76 1314.65,893.11 R16.1@1389.53,893.11
  L3-Signal w10: TP12.1@1220,1020 1215,1020 1055,1180 1055,2835 1150,2930 2260,2930 2280,2950 2280,3240 2525,3485 2855.96,3485 2910,3539.04 2910,3675 2880,3705 J3.1@2880,3720
  L6-BOT w10: TP12.1@1220,1020 1220,997.99 1335,882.99 ; 1324.76,882.99 C57.2@1389.65,882.99
"EAST DRIVE-": C54.2 J3.2 R15.1 TP11.1 | length 4693.8
  L1-TOP w10: TP11.1@1220,1260 1305,1175 1351.42,1175 R15.1@1384.53,1208.11
  L3-Signal w10: TP11.1@1220,1260 1215,1260 1075,1400 1075,2830.96 1157.04,2913 2273,2913 2300,2940 2300,3235.96 2532.04,3468 2863,3468 2930,3535 2930,3770 J3.2@2880,3820
  L6-BOT w10: TP11.1@1220,1260 1305,1175 1351.42,1175 C54.2@1389.65,1213.23
"EAST OC LATCH": J4.21 U27.14 | length 783.2
  L1-TOP w10: v1(7725,3065) U27.14@7725,3191.1
  L3-Signal w10: J4.21@7720,3720 7725,3715 v1(7725,3065)
"EAST TACH OUT": C4.1 C8.1 J4.3 R207.1 R212.1 R236.1 U2.1 | length 9949.5
  L1-TOP w10: C4.1@1495.12,780 1512.64,780 C8.1@1619.53,673.11 1619.53,707.99 1726.22,814.69 1764.69,814.69 v1(1770,820) 1775.31,814.69 U2.1@1854.65,814.69
  L3-Signal w10: v1(1770,820) 1710,760 1710,690 1795,605 2060,605 2105,650 2410.7,650 2420.7,660 2895,660 2930,695 2930,1225 2968,1263 v1@2968,1708 ; v1@2976.98,1715.01 2975,2295 3025,2345 3025,2405 3000,2430 3000,2610 2950,2660 2950,2810 3080,2940 3525,2940 3635,3050 3635,3330 3725,3420 3725,3865 3750,3890 6940,3890 6970,3860 6970,3790 6950,3770 6885,3770 6835,3720 J4.3@6820,3720
  L6-BOT w10: R207.1@1495.12,760 1532.64,760 R212.1@1619.53,673.11 1619.53,714.53 1725,820 v1(1770,820) ; R236.1@2814.88,1570 2814.88,1664.88 2870,1720 2980,1720 v1(2975,1715)
"EAST VEL IN": J3.13 R220.2 | length 4542
  L3-Signal w10: v1(1745,1360) 2435,1360 2520,1445 2520,1565 2530,1575 2540,1575 2540,2169.04 2805,2434.04 2805,2600 2795,2610 2795,2870 2990,3065 2990,3197.88 3195.12,3403 3403,3403 3500,3500 3630,3500 3645,3515 3645,3565 3605,3605 3540,3605 3480,3665 J3.13@3480,3720
  L6-BOT w10: v1(1745,1360) 1710,1395 1705,1395 1705,1465 1843,1603 2117,1603 2154.88,1565.12 R220.2@2180,1565.12
"EAST VEL OUT": C77.2 J4.10 R43.2 | length 10566
  L1-TOP w10: R43.2@2645.12,770 2645.12,754.88 2675,725 v1(2840,725)
  L4-Signal w10: v1(2785,3740) 2820,3740 2835,3725 2835,3680 2850,3665 3015,3665 3100,3580 3330,3580 v1(3370,3540)
  L3-Signal w10: v1(2785,3740) 2740,3740 2685,3795 2685,3875 2760,3950 6990,3950 J4.10@7120,3820 ; v1(2840,725) 2795,725 2585,935 2480,935 2430,885 1835,885 1742.27,977.73 1742.27,1162.73 1675,1230 1675,1400 1695,1420 1785,1420 1805,1440 1805,2320 2025,2540 2270,2540 2340,2610 2340,2680 2410,2750 2470,2750 3175,3455 3290,3455 3370,3535 v1(3370,3540)
  L6-BOT w10: C77.2@2775.12,790 2775.12,789.88 v1(2840,725)
EAST_ENCODER_BUF: J5.3 R141.1 R321.2 | length 2995.4
  L1-TOP w10: v1(6640,405) 6680,365 R141.1@6779.88,365
  L3-Signal w10: v1(6640,405) 6640,370 6750,260 8935,260 8965,230 9165,230 9200,265 J5.3@9200,280
  L6-BOT w10: v1(6640,405) 6680,365 R321.2@6779.88,365
EAST_ENCODER_IN: J5.6 R149.1 R168.1 | length 2463.6
  L1-TOP w10: R149.1@7190.12,875 7200,875 v1(7285,790) ; R168.1@7905.12,435 7950,435 v1(7995,390)
  L3-Signal w10: v1(7285,790) 7685,390 v1(7995,390) 8040,435 9250,435 9300,385 J5.6@9300,380
EAST_ENCODER_RTN: J5.8 R167.1 R332.1 | length 2516
  L1-TOP w10: R167.1@7905.12,555 7940.12,520 v1(7980,520)
  L3-Signal w10: v1(7290,865) 7640,515 7975,515 8035,455 9345,455 9400,400 J5.8@9400,380
  L6-BOT w10: R332.1@7190.12,875 7280,875 v1(7290,865)
EAST_OVERCURRENT_LATCH: U27.6 U32.95 | length 1200.7
  L1-TOP w10: U27.6@7675,2828.9 7675,2740 7703,2712 8463,2712 v1(8505,2670) 8505,2580 8582.2,2502.8 U32.95@8582.2,2449.21
EAST_OVERCURRENT_N: TP42.1 U32.27 U40.12 | length 6042.5
  L1-TOP w10: v1(8405,1630) 8405,1700 8503.46,1798.46 U32.27@8503.46,1850.79
  L4-Signal w10: v1(6205,555) 6235,555 6265,585 6265,615 6495,845 6760,845 6903,702 7022,702 7055,735 7055,1425 7125,1495 7125.96,1495 7160.96,1530 7160.96,1530.96 7184,1554 7433,1554 ; 7437,1558 7525,1470 7525,1415 7550,1390 7825,1390 8065,1630 v1(8405,1630)
  L3-Signal w10: v1(8405,1630) 8405,1695 8485,1775 9190,1775 9210,1755 9280,1755 9445,1920 9445,2760 9485,2800 TP42.1@9710,2800
  L6-BOT w10: v1(6205,555) 6220,570 U40.12@6291.57,570
EGND: J5.9 J5.11 R153.2 | length 89.9
  L1-TOP w10: R153.2@7195.12,1350 v1(7285,1350)
"EMERG STOP": J3.40 R272.2 R310.2 | length 2751.8
  L4-Signal w10: v1(4715,3210) 4715,3615 4730,3630 4730,3770 J3.40@4780,3820
  L3-Signal w10: v1(5165,2890) 5165,2880 5275,2770 v1(6100,2770)
  L6-BOT w10: v1(4715,3210) 4715,3180.12 R272.2@4660,3125.12 4660,3115 4705,3070 5270,3070 5290,3050 5290,2975 5230,2915 5180,2915 5155,2890 v1(5165,2890) ; v1(6100,2770) 6134.88,2804.88 R310.2@6134.88,2850
"EMERG STOP LATCH": J4.27 U30.16 | length 751.2
  L1-TOP w10: v1(8165,3110) U30.16@8165,3191.1
  L3-Signal w10: J4.27@8020,3720 8020,3345 8165,3200 v1(8165,3110)
EMERG_STOP_BUF_N: U32.18 U44.6 | length 1257.1
  L1-TOP w10: v1(8200,1990) 8320,1990 8381.57,2051.57 U32.18@8420.79,2051.57
  L6-BOT w10: U44.6@7928.43,2510 7990,2510 8040,2560 8255,2560 8305,2510 8305,2045 8250,1990 v1(8200,1990)
EMERG_STOP_LATCH: U30.4 U32.89 | length 1128.2
  L1-TOP w10: v1(8110,2920) 8115,2915 U30.4@8115,2828.9 ; U32.89@8700.32,2449.21 8700.32,2655.31 v1(8715,2670)
  L4-Signal w10: v1(8110,2920) 8110,2750 8131,2729 8656,2729 v1(8715,2670)
"HA EMERG E": J3.35 U39.2 | length 2758.2
  L4-Signal w10: J3.35@4580,3720 4525,3665 4410,3665 4370,3625 4370,3540 4530,3380 4530,3160 4555,3135 5430,3135 v1(5510,3215)
  L6-BOT w10: U39.2@5285,2615.16 5285,2590 5260,2565 5210,2565 5190,2585 5190,2840 5325,2975 5325,3120 5375,3170 5465,3170 v1(5510,3215)
"HA EMERG E LATCH": J4.34 U33.17 | length 1006.7
  L1-TOP w10: v1(8650,3060) U33.17@8650,3170
  L3-Signal w10: J4.34@8320,3820 8370,3770 8370,3580 8650,3300 v1(8650,3060)
"HA EMERG W": J3.34 U18.6 | length 2185.3
  L1-TOP w10: v1(5320,3210) 5305,3195 5305,2965 5200,2860 5200,2580 5210,2570 5310,2570 5335,2595 U18.6@5335,2615.16
  L4-Signal w10: v1(4830,3540) 5035,3335 5230,3335 5320,3245 v1(5320,3210)
  L6-BOT w10: J3.34@4480,3820 4430,3770 4430,3610 4535,3505 4795,3505 v1(4830,3540)
"HA EMERG W LATCH": J4.33 U33.18 | length 819.2
  L1-TOP w10: v1(8605,3105) U33.18@8605,3191.1
  L3-Signal w10: J4.33@8320,3720 8320,3585 8605,3300 v1(8605,3105)
"HA OS LATCH": J4.18 U27.17 | length 813.9
  L1-TOP w10: v1(7575,3110) U27.17@7575,3191.1
  L3-Signal w10: J4.18@7520,3820 7575,3765 v1(7575,3110)
"HA STOP E": J3.33 U18.2 | length 2391.6
  L1-TOP w10: U18.2@5535,2615.16 5535,2575 5550,2560 5630,2560 5650,2580 5650,3160 v1(5705,3215)
  L3-Signal w10: v1(5185,3620) 5185,3525 5350,3360 5565,3360 5705,3220 v1(5705,3215)
  L6-BOT w10: J3.33@4480,3700 J3.33@4480,3730 ; J3.33@4480,3720 4540,3660 4785,3660 4875,3570 5135,3570 v1(5185,3620)
"HA STOP E LATCH": J4.32 U30.11 | length 961.9
  L1-TOP w10: v1(8415,3065) U30.11@8415,3191.1
  L3-Signal w10: J4.32@8220,3820 8270,3770 8270,3575 8415,3430 v1(8415,3065)
"HA STOP W": J3.32 U13.6 | length 1196.3
  L1-TOP w10: J3.32@4380,3820 4430,3770 4430,3610 4495,3545 v1(4670,3545) ; U13.6@4760,2910.16 4760,3195 v1(4775,3210)
  L3-Signal w10: v1(4670,3545) 4775,3440 v1(4775,3210) 4765,3220
"HA STOP W LATCH": J4.31 U30.12 | length 785.8
  L1-TOP w10: v1(8365,3110) U30.12@8365,3191.1
  L3-Signal w10: J4.31@8220,3720 8220,3540 8255,3505 8300,3505 8375,3430 8375,3120 v1(8365,3110)
"HA VEL FEEDBACK": J3.17 R196.1 R226.2 TP16.1 U3.14 | length 7476.6
  L1-TOP w10: U3.14@2383.07,2698.11 v1@2454.65,2698.11 ; v1(2459.65,2693.11) 2459.65,2704.65 2580,2825 2700,2825 2715,2810 2715,2620 2780,2555 3050,2555 3100,2605 TP16.1@3100,2700
  L4-Signal w10: TP16.1@3100,2700 3100,2655 3130,2625 3575,2625 3620,2670 3620,3195 3680,3255 J3.17@3680,3720
  L6-BOT w10: R196.1@980,945.12 1045.12,945.12 1100,1000 1100,2855 1175,2930 2050,2930 2070,2910 2070,2825 2090,2805 2150,2805 2195,2760 2195,2650 2245,2600 2335,2600 2409.53,2674.53 2409.53,2802.99 2429.65,2823.11 2569.65,2823.11 2579.65,2813.11 2579.65,2795.35 2613,2762 2757,2762 2845,2850 3020,2850 3100,2770 TP16.1@3100,2700 ; R226.2@2409.53,2743.23 v1(2459.65,2693.11)
HA_EMERG_E_LATCH: U32.78 U33.3 | length 705.7
  L1-TOP w10: U33.3@8605,2828.9 8605,2750 8643,2712 8918,2712 v1(8960,2670) 8960,2575 8916.85,2531.85 U32.78@8916.85,2449.21
HA_EMERG_EAST_BUF_N: U32.1 U43.8 | length 1612.1
  L1-TOP w10: v1(8200,2480) 8220,2480 8255,2445 8362.01,2445 U32.1@8420.79,2386.22
  L3-Signal w10: v1(7215,2370) 7215,2365 7258,2322 7412.96,2322 7440.96,2350 7650,2350 7825,2525 8170,2525 8200,2495 v1(8200,2480)
  L6-BOT w10: U43.8@7078.43,2490 7175,2490 7215,2450 v1(7215,2370)
HA_EMERG_W_LATCH: U32.79 U33.2 | length 758.4
  L1-TOP w10: U33.2@8555,2870 8555,2745 8605,2695 8900,2695 v1(8925,2670) 8925,2565 8897.17,2537.17 U32.79@8897.17,2449.21
HA_EMERG_WEST_BUF_N: U32.54 U45.4 | length 635.2
  L1-TOP w10: U32.54@9019.21,1972.83 9152.17,1972.83 v1(9240,1885)
  L6-BOT w10: v1(9240,1885) 9215,1860 9215,1665 9290,1590 U45.4@9331.57,1590
HA_OVERSPEED_LATCH: U27.3 U32.99 | length 1247.7
  L1-TOP w10: U27.3@7525,2828.9 7525,2755 7610,2670 v1(8400,2670) 8400,2595 8503.46,2491.54 U32.99@8503.46,2449.21
HA_OVERSPEED_N: TP39.1 U32.28 U40.8 | length 5224.9
  L1-TOP w10: v1(8440,1630) 8440,1710 8523.15,1793.15 U32.28@8523.15,1850.79
  L4-Signal w10: v1(6210,350) 6270,350 6350,430 6350,675 6502.4,827.4 6747.6,827.4 6890,685 7030,685 7062,717 ; 7062,717.96 7075,730.96 7075,1420 7130,1475 7390,1475 7495,1370 7840,1370 8075,1605 8415,1605 v1(8440,1630)
  L3-Signal w10: v1(8440,1630) 8440,1665 8530,1755 9185.96,1755 9205.96,1735 9285,1735 9450,1900 9450.96,1900 9520.96,1970 TP39.1@9630,1970
  L6-BOT w10: v1(6210,350) 6230,370 U40.8@6291.57,370
HA_STOP_E_LATCH: U30.9 U32.81 | length 1048.8
  L1-TOP w10: U30.9@8365,2828.9 8365,2915 v1(8385,2935) ; U32.81@8857.8,2449.21 8857.8,2537.8 8890,2570 v1(8890,2670)
  L6-BOT w10: v1(8385,2935) 8385,2789 8428,2746 8814,2746 v1(8890,2670)
HA_STOP_EAST_BUF_N: U32.13 U42.10 | length 2132.4
  L1-TOP w10: v1(8200,2165) 8325,2165 8340,2150 U32.13@8420.79,2150
  L3-Signal w10: v1(6505,2135) 6580,2135 6656,2059 7482.83,2059 7528.83,2105 7870,2105 7930,2165 v1(8200,2165)
  L6-BOT w10: U42.10@6421.57,2060 6465,2060 6480,2075 6480,2100 6505,2125 v1(6505,2135)
HA_STOP_W_LATCH: U30.8 U32.82 | length 1055
  L1-TOP w10: U30.8@8315,2828.9 v1(8315,2920) ; U32.82@8838.11,2449.21 8838.11,2543.11 8855,2560 v1(8855,2670)
  L6-BOT w10: v1(8315,2920) 8315,2762 8348,2729 8796,2729 v1(8855,2670)
HA_STOP_WEST_BUF_N: U32.15 U42.6 | length 2076.5
  L1-TOP w10: v1(8200,2095) 8325,2095 8340.63,2110.63 U32.15@8420.79,2110.63
  L3-Signal w10: v1(6520,2025) 7496.92,2025 7536.92,2065 7885,2065 7930,2110 8185,2110 v1(8200,2095)
  L6-BOT w10: v1(6520,2025) 6560,2025 6575,2010 U42.6@6605,2010 ; U42.6@6618.43,2010 U42.6@6655,2010
"HORIZON STOP": J3.31 U13.2 | length 1684.1
  L1-TOP w10: U13.2@4960,2910.16 4960,2930 4990,2960 5100,2960 5135,2995 v1(5135,3215)
  L4-Signal w10: v1(4415,3555) 4550,3420 4550,3195 4590,3155 5110,3155 5135,3180 v1(5135,3215)
  L3-Signal w10: J3.31@4380,3720 4380,3590 v1(4415,3555)
"HORIZON STOP LATCH": J4.39 U33.12 | length 809.2
  L1-TOP w10: v1(8905,3110) U33.12@8905,3191.1
  L3-Signal w10: J4.39@8620,3720 8620,3560 8905,3275 v1(8905,3110)
HORIZON_STOP_BUF_N: U32.17 U42.2 | length 2235.8
  L1-TOP w10: v1(8200,2025) 8330,2025 8376.26,2071.26 U32.17@8420.79,2071.26
  L3-Signal w10: v1(6845,1920) 6845,1910 6885,1870 7390,1870 7545,2025 7895,2025 7945,2075 8150,2075 v1(8200,2025)
  L6-BOT w10: U42.2@6618.43,2210 6660,2210 6700,2250 6735,2250 6755,2230 6755,2059.04 6785,2029.04 6785,1980 v1(6845,1920)
HORIZON_STOP_LATCH: U32.71 U33.8 | length 1452.9
  L1-TOP w10: v1(8790,2950) 8790,2925 8855,2860 U33.8@8855,2828.9 ; U32.71@9019.21,2307.48 9122.48,2307.48 9190,2375 v1(9240,2375)
  L3-Signal w10: v1(8790,2950) 8790,2785 8846,2729 9236,2729 9320,2645 9320,2455 v1(9240,2375)
"HP STOP": J3.44 U18.8 | length 1447.7
  L1-TOP w10: U18.8@5235,2615.16 5235,2850 5335,2950 5335,3170 v1@5380,3215 ; v1@5380,3225 v1@5380,3215 ; v1(5385,3215) v1@5380,3215
  L3-Signal w10: J3.44@4980,3820 5025,3775 5025,3609.04 5385,3249.04 v1(5385,3215)
"HP STOP LATCH": J4.28 U30.15 | length 971.9
  L1-TOP w10: v1(8215,3060) U30.15@8215,3191.1
  L3-Signal w10: J4.28@8020,3820 8070,3770 8070,3340 8215,3195 v1(8215,3060)
HP_STOP_BUF_N: U32.53 U45.2 | length 1290.6
  L1-TOP w10: U32.53@9019.21,1953.15 9136.85,1953.15 v1(9240,1850) 9270,1850 9295,1875 9295,1960 9320,1985 9500,1985 9540,1945 9540,1605 9500,1565 v1(9430,1565)
  L6-BOT w10: U45.2@9331.57,1490 9370,1490 9430,1550 v1(9430,1565)
HP_STOP_LATCH: U30.5 U32.87 | length 1077.9
  L1-TOP w10: U30.5@8165,2828.9 8165,2910 v1(8175,2920) ; U32.87@8739.68,2449.21 8739.68,2659.69 v1(8750,2670)
  L4-Signal w10: v1(8175,2920) 8175,2785 8214,2746 8674,2746 v1(8750,2670)
IBD1: R64.2 R107.1 TP30.1 U6.7 U20.6 | length 2090.4
  L1-TOP w10: U6.7@3570,421.57 3591.57,421.57 3620,450 3745,450 3765.12,429.88 ; R64.2@3765.12,380 3765.12,429.88 ; TP30.1@4370,405 TP30.1@4370,390 ; U20.6@5261.57,510 5256.57,515 5220,515 5205,500 5205,459.88 R107.1@5150,404.88 5150,345 5127,322 4443,322 4375,390 TP30.1@4370,390 ; 3765.12,429.88 3769.88,429.88 3795,455 3895,455 3930,420 3930,335 3945,320 4075,320 4120,365 4345,365 TP30.1@4370,390
IBD2: R59.2 R84.1 TP32.1 U6.8 U11.8 | length 2370.5
  L1-TOP w10: U6.8@3570,618.43 3570,655 3590,675 3730,675 3765,710 3765,730 R59.2@3765.12,730 3775.12,720 4135,720 4180,765 ; R84.1@4250,1025 4250,935.12 ; U11.8@4638.43,1090.12 4625,1076.69 4625,955.12 4540,870.12 4315,870.12 4250,935.12 ; TP32.1@4670,390 4670,400 4615,455 4280,455 4220,515 4220,680 4180,720 4180,895 4220.12,935.12 4250,935.12
IBD3: R51.2 R273.1 TP31.1 U6.1 U37.6 | length 2259.1
  L1-TOP w10: R51.2@3165.12,380 3228.43,380 U6.1@3270,421.57 3270,485 3275,485 v1(3300,510)
  L3-Signal w10: TP31.1@4520,390 4520,435 v1(4725,640)
  L6-BOT w10: v1(3300,510) 3365,510 3390,485 3625,485 3790,320 4460,320 4520,380 TP31.1@4520,390 ; v1(4725,640) 4750,665 U37.6@4750,710 ; U37.6@4750,738.43 4750,860 4795.12,905.12 4795.12,990 R273.1@4785.12,1000
IBE: R56.2 R87.1 TP27.1 U7.7 U14.6 | length 2164.8
  L1-TOP w10: U7.7@3516.57,2095 3511.57,2090 3440,2090 3360.12,2010.12 3360.12,1879.88 3470,1770 3815,1770 3860,1815 4240,1815 4265,1840 4265,1945 TP27.1@4170,2040 4330,2200 4425,2200 4485.12,2260.12 R87.1@4485.12,2275 4530,2275 4570,2315 U14.6@4671.57,2315
IBN: R60.2 R281.1 TP25.1 U7.14 U12.6 | length 2308.9
  L1-TOP w10: U7.14@3750,2395 U7.14@3713.43,2395 3778.43,2460 R60.2@3814.88,2460 3814.88,2470.88 3857,2513 3957,2513 4130,2340 TP25.1@4170,2340 ; U12.6@4870,1511.57 4870,1465 4890,1445 4960,1445 v1(4975,1430)
  L6-BOT w10: TP25.1@4170,2340 4170,2320 4415,2075 4415,1865 4445,1835 4535,1835 4555,1855 4595,1855 4625,1825 4760,1825 4770,1835 4830,1835 4960,1705 4960,1554.88 R281.1@5010,1504.88 5010,1465 v1(4975,1430)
